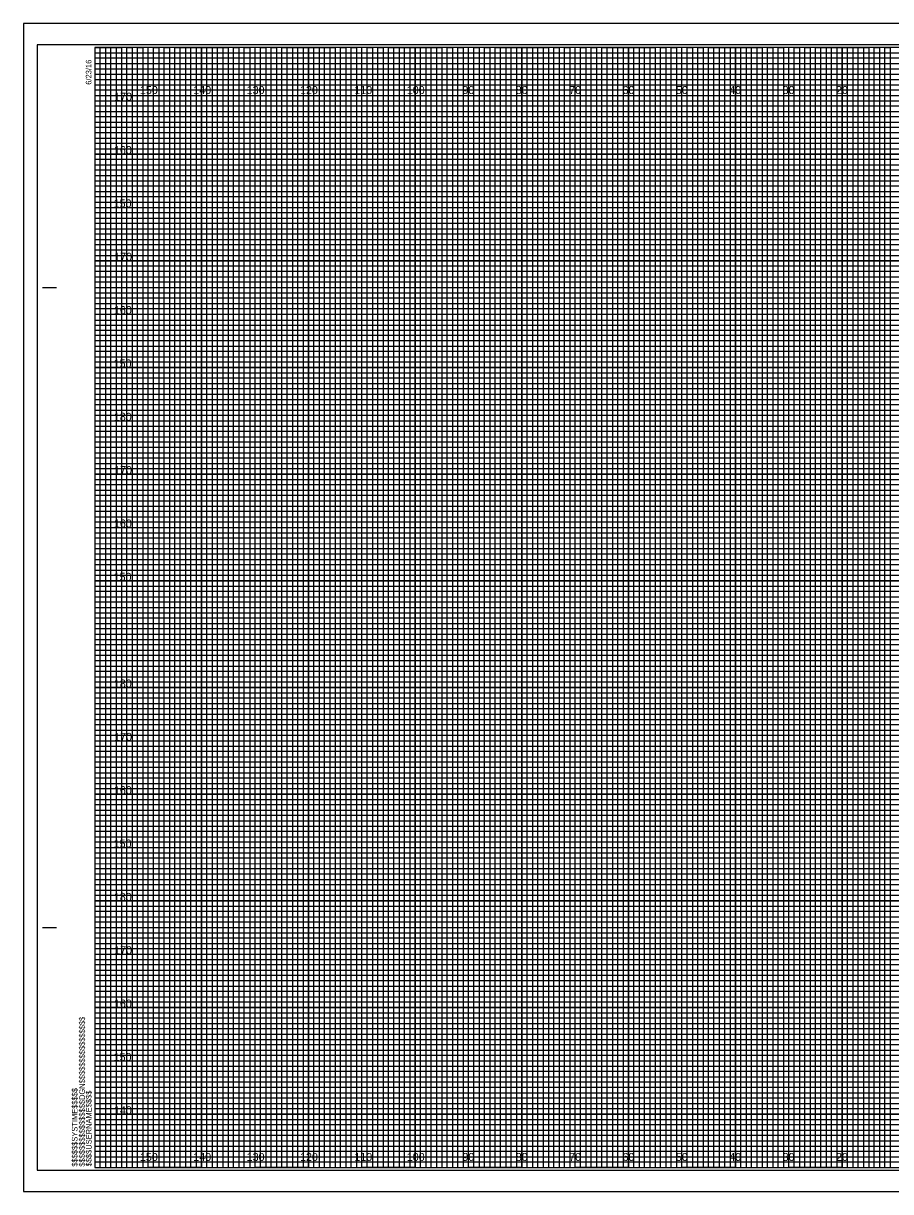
# Model space of a CAD drawing. Extents: x -13 to 323, y -5 to 654.
# Drawn here: x -13.4 to 149.1, y 435.5 to 654.5 of the extents above; entities that cross this region are included whole.
import ezdxf

# ---------------------------------------------------------------- set-up
doc = ezdxf.new("R2010")
doc.units = 0
for name, color, linetype in [('Exist Cross Section Cell', 7, 'Continuous'), ('Exist XS Center Line Elevation Label', 7, 'Continuous'), ('Exist XS Ground Line', 7, 'Continuous'), ('Prop CMT Guardrail Graphics', 7, 'Continuous'), ('Prop CMT Pvmt Course 1', 7, 'Continuous'), ('Prop CMT Pvmt Course 2', 7, 'Continuous'), ('Prop CMT Pvmt Course 3', 7, 'Continuous'), ('Prop CMT Shld Paved Course 1', 7, 'Continuous'), ('Prop CMT Shld Paved Course 2', 7, 'Continuous'), ('Prop CMT Subgrade Earthwork', 7, 'Continuous'), ('Scratch_Level_0', 7, 'Continuous')]:
    doc.layers.add(name, color=color, linetype=linetype)

msp = doc.modelspace()

# ---------------------------------------------------------------- linework, layer by layer
at = {"layer": 'Exist XS Center Line Elevation Label'}
for points in [[(0, 650), (5, 650), (5, 440), (15, 440), (15, 650), (25, 650), (25, 440), (35, 440), (35, 650), (45, 650), (45, 440), (55, 440), (55, 650), (65, 650), (65, 440), (75, 440), (75, 650), (85, 650), (85, 440), (95, 440), (95, 650), (105, 650), (105, 440), (115, 440), (115, 650), (125, 650), (125, 440), (135, 440), (135, 650), (145, 650), (145, 440), (155, 440)], [(0, 645), (275, 645)], [(0, 625), (320, 625), (320, 635), (0, 635)], [(0, 605), (320, 605), (320, 615), (0, 615)], [(0, 585), (320, 585), (320, 595), (0, 595)], [(0, 565), (320, 565), (320, 575), (0, 575)], [(0, 545), (320, 545), (320, 555), (0, 555)], [(0, 525), (320, 525), (320, 535), (0, 535)], [(0, 505), (320, 505), (320, 515), (0, 515)], [(0, 485), (320, 485), (320, 495), (0, 495)], [(0, 465), (320, 465), (320, 475), (0, 475)], [(0, 445), (320, 445), (320, 455), (0, 455)]]:
    msp.add_lwpolyline(points, dxfattribs=at)
at = {"layer": 'Exist XS Ground Line'}
for p, q in [((10, 650), (0, 650)), ((10, 440), (10, 650)), ((30, 650), (20, 650)), ((20, 650), (20, 440)), ((30, 440), (30, 650)), ((50, 650), (40, 650)), ((40, 650), (40, 440)), ((50, 440), (50, 650)), ((70, 650), (60, 650)), ((60, 650), (60, 440)), ((70, 440), (70, 650)), ((90, 650), (80, 650)), ((80, 650), (80, 440)), ((90, 440), (90, 650)), ((110, 650), (100, 650)), ((100, 650), (100, 440)), ((110, 440), (110, 650)), ((130, 650), (120, 650)), ((120, 650), (120, 440)), ((130, 440), (130, 650)), ((150, 650), (140, 650)), ((140, 650), (140, 440)), ((20, 440), (10, 440)), ((40, 440), (30, 440)), ((60, 440), (50, 440)), ((80, 440), (70, 440)), ((100, 440), (90, 440)), ((120, 440), (110, 440)), ((140, 440), (130, 440))]:
    msp.add_line(p, q, dxfattribs=at)
for points in [[(0, 640), (320, 640), (320, 630), (0, 630)], [(0, 620), (320, 620), (320, 610), (0, 610)], [(0, 600), (320, 600), (320, 590), (0, 590)], [(0, 580), (320, 580), (320, 570), (0, 570)], [(0, 560), (320, 560), (320, 550), (0, 550)], [(0, 540), (320, 540), (320, 530), (0, 530)], [(0, 520), (320, 520), (320, 510), (0, 510)], [(0, 500), (320, 500), (320, 490), (0, 490)], [(0, 480), (320, 480), (320, 470), (0, 470)], [(0, 460), (320, 460), (320, 450), (0, 450)]]:
    msp.add_lwpolyline(points, dxfattribs=at)
at = {"layer": 'Prop CMT Pvmt Course 1'}
for p, q in [((323.3, 654.5), (-13.4, 654.5)), ((-13.4, 654.5), (-13.4, 435.5)), ((-13.4, 435.5), (323.3, 435.5))]:
    msp.add_line(p, q, dxfattribs=at)
at = {"layer": 'Prop CMT Pvmt Course 2'}
msp.add_lwpolyline([(-13.4, 435.5), (323.3, 435.5), (323.3, 654.5), (-13.4, 654.5)], close=True, dxfattribs=at)
at = {"layer": 'Prop CMT Pvmt Course 3'}
msp.add_lwpolyline([(-10.8, 439.5), (322.4, 439.5), (322.4, 650.5), (-10.8, 650.5)], close=True, dxfattribs=at)
at = {"layer": 'Prop CMT Shld Paved Course 1'}
for p, q in [((-9.8, 605), (-7.3, 605)), ((-9.7, 605), (-7.2, 605)), ((-9.8, 485), (-7.3, 485)), ((-9.7, 485), (-7.2, 485)), ((0, 440), (0, 440)), ((0, 440), (0, 440)), ((0, 440), (0, 440)), ((0, 440), (0, 440)), ((0, 440), (0, 440)), ((0, 440), (0, 440)), ((0, 440), (0, 440))]:
    msp.add_line(p, q, dxfattribs=at)
msp.add_lwpolyline([(320, 650), (0, 650), (0, 440), (320, 440)], close=True, dxfattribs=at)
at = {"layer": 'Prop CMT Shld Paved Course 2'}
for points in [[(0, 440), (1, 440), (1, 650), (2, 650), (2, 440)], [(2, 440), (3, 440), (3, 650), (4, 650), (4, 440)], [(5, 440), (6, 440), (6, 650), (7, 650), (7, 440)], [(7, 440), (8, 440), (8, 650), (9, 650), (9, 440)], [(10, 440), (11, 440), (11, 650), (12, 650), (12, 440)], [(12, 440), (13, 440), (13, 650), (14, 650), (14, 440)], [(15, 440), (16, 440), (16, 650), (17, 650), (17, 440)], [(17, 440), (18, 440), (18, 650), (19, 650), (19, 440)], [(20, 440), (21, 440), (21, 650), (22, 650), (22, 440)], [(22, 440), (23, 440), (23, 650), (24, 650), (24, 440)], [(25, 440), (26, 440), (26, 650), (27, 650), (27, 440)], [(27, 440), (28, 440), (28, 650), (29, 650), (29, 440)], [(30, 440), (31, 440), (31, 650), (32, 650), (32, 440)], [(32, 440), (33, 440), (33, 650), (34, 650), (34, 440)], [(35, 440), (36, 440), (36, 650), (37, 650), (37, 440)], [(37, 440), (38, 440), (38, 650), (39, 650), (39, 440)], [(40, 440), (41, 440), (41, 650), (42, 650), (42, 440)], [(42, 440), (43, 440), (43, 650), (44, 650), (44, 440)], [(45, 440), (46, 440), (46, 650), (47, 650), (47, 440)], [(47, 440), (48, 440), (48, 650), (49, 650), (49, 440)], [(50, 440), (51, 440), (51, 650), (52, 650), (52, 440)], [(52, 440), (53, 440), (53, 650), (54, 650), (54, 440)], [(55, 440), (56, 440), (56, 650), (57, 650), (57, 440)], [(57, 440), (58, 440), (58, 650), (59, 650), (59, 440)], [(60, 440), (61, 440), (61, 650), (62, 650), (62, 440)], [(62, 440), (63, 440), (63, 650), (64, 650), (64, 440)], [(65, 440), (66, 440), (66, 650), (67, 650), (67, 440)], [(67, 440), (68, 440), (68, 650), (69, 650), (69, 440)], [(70, 440), (71, 440), (71, 650), (72, 650), (72, 440)], [(72, 440), (73, 440), (73, 650), (74, 650), (74, 440)], [(75, 440), (76, 440), (76, 650), (77, 650), (77, 440)], [(77, 440), (78, 440), (78, 650), (79, 650), (79, 440)], [(80, 440), (81, 440), (81, 650), (82, 650), (82, 440)], [(82, 440), (83, 440), (83, 650), (84, 650), (84, 440)], [(85, 440), (86, 440), (86, 650), (87, 650), (87, 440)], [(87, 440), (88, 440), (88, 650), (89, 650), (89, 440)], [(90, 440), (91, 440), (91, 650), (92, 650), (92, 440)], [(92, 440), (93, 440), (93, 650), (94, 650), (94, 440)], [(95, 440), (96, 440), (96, 650), (97, 650), (97, 440)], [(97, 440), (98, 440), (98, 650), (99, 650), (99, 440)], [(100, 440), (101, 440), (101, 650), (102, 650), (102, 440)], [(102, 440), (103, 440), (103, 650), (104, 650), (104, 440)], [(105, 440), (106, 440), (106, 650), (107, 650), (107, 440)], [(107, 440), (108, 440), (108, 650), (109, 650), (109, 440)], [(110, 440), (111, 440), (111, 650), (112, 650), (112, 440)], [(112, 440), (113, 440), (113, 650), (114, 650), (114, 440)], [(115, 440), (116, 440), (116, 650), (117, 650), (117, 440)], [(117, 440), (118, 440), (118, 650), (119, 650), (119, 440)], [(120, 440), (121, 440), (121, 650), (122, 650), (122, 440)], [(122, 440), (123, 440), (123, 650), (124, 650), (124, 440)], [(125, 440), (126, 440), (126, 650), (127, 650), (127, 440)], [(127, 440), (128, 440), (128, 650), (129, 650), (129, 440)], [(130, 440), (131, 440), (131, 650), (132, 650), (132, 440)], [(132, 440), (133, 440), (133, 650), (134, 650), (134, 440)], [(135, 440), (136, 440), (136, 650), (137, 650), (137, 440)], [(137, 440), (138, 440), (138, 650), (139, 650), (139, 440)], [(140, 440), (141, 440), (141, 650), (142, 650), (142, 440)], [(142, 440), (143, 440), (143, 650), (144, 650), (144, 440)], [(145, 440), (146, 440), (146, 650), (147, 650), (147, 440)], [(147, 440), (148, 440), (148, 650), (149, 650), (149, 440)]]:
    msp.add_lwpolyline(points, dxfattribs=at)
at = {"layer": 'Prop CMT Subgrade Earthwork'}
for p, q in [((10, 440), (10, 650)), ((20, 440), (20, 650)), ((30, 440), (30, 650)), ((40, 440), (40, 650)), ((50, 440), (50, 650)), ((60, 440), (60, 650)), ((70, 440), (70, 650)), ((80, 440), (80, 650)), ((90, 440), (90, 650)), ((100, 440), (100, 650)), ((110, 440), (110, 650)), ((120, 440), (120, 650)), ((130, 440), (130, 650)), ((140, 440), (140, 650)), ((0, 640), (320, 640)), ((0, 630), (320, 630)), ((0, 620), (320, 620)), ((0, 610), (320, 610)), ((0, 600), (320, 600)), ((0, 590), (320, 590)), ((0, 580), (320, 580)), ((0, 570), (320, 570)), ((0, 560), (320, 560)), ((0, 550), (320, 550)), ((0, 540), (320, 540)), ((0, 530), (320, 530)), ((0, 520), (320, 520)), ((0, 510), (320, 510)), ((0, 500), (320, 500)), ((0, 490), (320, 490)), ((0, 480), (320, 480)), ((0, 470), (320, 470)), ((0, 460), (320, 460)), ((0, 450), (320, 450))]:
    msp.add_line(p, q, dxfattribs=at)
at = {"layer": 'Scratch_Level_0'}
for p, q in [((0, 649), (260, 649)), ((260, 647.98), (0, 647.98)), ((0, 647.98), (0, 647)), ((0, 647), (260, 647)), ((260, 645.89), (0, 645.89)), ((0, 645.89), (0, 644)), ((0, 644), (320, 644))]:
    msp.add_line(p, q, dxfattribs=at)
for points in [[(0, 643), (270, 643), (320, 643), (320, 642), (0, 642)], [(0, 641), (320, 641), (320, 639), (0, 639)], [(0, 638), (320, 638), (320, 637), (0, 636.98)], [(0, 636), (320, 636), (320, 634), (0, 634)], [(0, 633), (320, 633), (320, 632), (0, 632)], [(0, 631), (320, 631), (320, 629), (0, 629)], [(0, 628), (320, 628), (320, 627), (0, 627)], [(0, 626), (320, 626), (320, 624), (0, 624)], [(0, 623), (320, 623), (320, 622), (0, 622)], [(0, 621), (320, 621), (320, 619), (0, 619)], [(0, 618), (320, 618), (320, 617), (0, 617)], [(0, 616), (320, 616), (320, 613.95), (320, 613), (320, 612), (0, 612)], [(0, 614), (320, 614), (320, 613), (0, 613)], [(0, 611), (320, 611), (320, 609), (0, 609.03)], [(0, 609.03), (320, 609), (320, 608), (0, 608)], [(0, 607), (320, 607), (320, 606), (0, 606)], [(0, 604), (320, 604), (320, 603), (0, 603)], [(0, 602), (320, 602), (320, 601), (0, 601)], [(-0.07, 598.89), (320, 598.89), (320, 597.88), (-0.07, 597.88)], [(0, 597), (320, 597), (320, 596), (0, 596)], [(0, 594), (320, 594), (320, 593), (0, 593)], [(0, 592), (320, 592), (320, 591), (0, 591)], [(0, 589), (320, 589), (320, 588), (0, 588)], [(0, 587), (320, 587), (320, 586), (0, 586)], [(0, 584), (320, 584), (320, 583), (0, 583)], [(0, 582), (320, 582), (320, 581), (0, 581)], [(0, 579), (320, 579), (319.99, 577.98), (0, 578)], [(0, 577), (320, 577), (320, 576), (0, 576)], [(0, 574), (320, 574), (320, 573), (0, 573)], [(0, 572), (320, 572), (320, 571), (0, 571)], [(0, 569), (320, 569), (320, 568), (0, 568)], [(0, 567), (320, 567), (320, 566), (0, 566)], [(0, 564), (320, 564), (320, 563), (0, 563)], [(0, 562), (320, 562), (320, 561), (0, 561)], [(0, 559), (320, 559), (320, 558), (0, 558)], [(0, 556.99), (320.07, 556.91), (320, 556), (0, 556)], [(0, 554), (320, 554), (320, 553), (0, 553)], [(0, 552), (320, 552), (320, 551), (0, 551)], [(0, 549), (320, 549), (320, 548), (0, 548)], [(0, 547), (320, 547), (320, 546), (0, 546)], [(0, 544), (320, 544), (320, 543), (0, 543)], [(0, 542), (320, 542), (320, 541), (0, 541)], [(0, 539), (320, 539), (320, 538), (0, 538)], [(0, 537), (320, 537), (320, 536), (0, 536)], [(0, 534), (320, 534), (320, 533), (0, 533)], [(0, 532), (320, 532), (320, 531), (0, 531)], [(0, 529), (320, 529), (320, 528), (0, 528)], [(0, 527), (320, 527), (320, 526), (0, 526)], [(0, 524), (320, 524), (320, 523), (0, 523)], [(0, 522), (320, 522), (320, 521), (0, 521)], [(0, 519), (320, 519), (319.99, 517.98), (0, 518)], [(0, 517), (320, 517), (320, 516), (0, 516)], [(0, 514), (320, 514), (320, 513), (0, 513)], [(0, 512), (320, 512), (320, 511), (0, 511)], [(0, 509), (320, 509), (320, 508), (0, 508)], [(0, 507), (320, 507), (320, 506), (0, 506)], [(0, 504), (320, 504), (320, 503), (0, 503)], [(0, 502), (320, 502), (320, 501), (0, 501)], [(0, 499), (320, 499), (320, 498), (0, 498)], [(0, 496.99), (320.07, 496.91), (320, 496), (0, 496)], [(0, 494), (320, 494), (320, 493), (0, 493)], [(0, 492), (320, 492), (320, 491), (0, 491)], [(0, 489), (320, 489), (320, 488), (0, 488)], [(0, 487), (320, 487), (320, 486), (0, 486)], [(0, 484), (320, 484), (320, 483), (0, 483)], [(0, 482), (320, 482), (320, 481), (0, 481)], [(0, 479), (320, 479), (320, 478), (0, 478)], [(0, 477), (320, 477), (320, 476), (0, 476)], [(0, 474), (320, 474), (320, 473), (0, 473)], [(0, 472), (320, 472), (320, 471), (0, 471)], [(0, 469), (320, 469), (320, 468), (0, 468)], [(0, 467), (320, 467), (320, 466), (0, 466)], [(0, 464), (320, 464), (320, 463), (0, 463)], [(0, 462), (320, 462), (320, 461), (0, 461)], [(0, 459), (320, 459), (320, 458), (0, 458)], [(0, 457), (320, 457), (320, 456), (0, 456)], [(0, 454), (320, 454), (320, 453), (0, 453)], [(0, 452), (320, 452), (320, 451), (0, 451)], [(0, 449), (320, 449), (320, 448), (0, 448)], [(0, 447), (320, 447), (320, 446), (0, 446)], [(0, 444), (320, 444), (320, 443), (0, 443)], [(0, 442), (320, 442), (320, 441), (0, 441)]]:
    msp.add_lwpolyline(points, dxfattribs=at)

# ---------------------------------------------------------------- texts
at = {"layer": 'Exist Cross Section Cell'}
for s, p in [('150', (8.44, 641.25)), ('140', (18.44, 641.25)), ('130', (28.44, 641.25)), ('120', (38.44, 641.25)), ('110', (48.62, 641.25)), ('100', (58.44, 641.25)), ('90', (68.86, 641.25)), ('80', (78.86, 641.25)), ('70', (88.86, 641.25)), ('60', (98.86, 641.25)), ('50', (108.86, 641.25)), ('40', (118.86, 641.25)), ('30', (128.86, 641.25)), ('20', (138.86, 641.25)), ('150', (8.44, 441.25)), ('140', (18.44, 441.25)), ('130', (28.44, 441.25)), ('120', (38.44, 441.25)), ('110', (48.62, 441.25)), ('100', (58.44, 441.25)), ('90', (68.86, 441.25)), ('80', (78.86, 441.25)), ('70', (88.86, 441.25)), ('60', (98.86, 441.25)), ('50', (108.86, 441.25)), ('40', (118.86, 441.25)), ('30', (128.86, 441.25)), ('20', (138.86, 441.25))]:
    msp.add_text(s, height=1.5, dxfattribs=at).set_placement(p)
at = {"layer": 'Prop CMT Guardrail Graphics'}
for s, p in [('170', (3.61, 640)), ('160', (3.57, 630)), ('150', (3.52, 620)), ('170', (3.61, 610)), ('160', (3.57, 600)), ('150', (3.52, 590)), ('180', (3.55, 580)), ('170', (3.61, 570)), ('160', (3.57, 560)), ('150', (3.52, 550)), ('180', (3.55, 530)), ('170', (3.61, 520)), ('160', (3.57, 510)), ('150', (3.52, 500)), ('180', (3.55, 490)), ('170', (3.61, 480)), ('160', (3.57, 470)), ('150', (3.52, 460)), ('140', (3.57, 450))]:
    msp.add_text(s, height=1.5, dxfattribs=at).set_placement(p)
at = {"layer": 'Prop CMT Shld Paved Course 1'}
for s, p in [('6/23/16', (-0.65, 643)), ('$$$$$$$$$$$$$$$$DGN$$$$$$$$$$$$$$$$', (-1.88, 440.18)), ('$$$$$$SYSTIME$$$$$', (-3.26, 440.18)), ('$$$$USERNAME$$$$', (-0.62, 440.23))]:
    msp.add_text(s, height=1.05, rotation=90, dxfattribs=at).set_placement(p)

doc.saveas('drawing.dxf')
